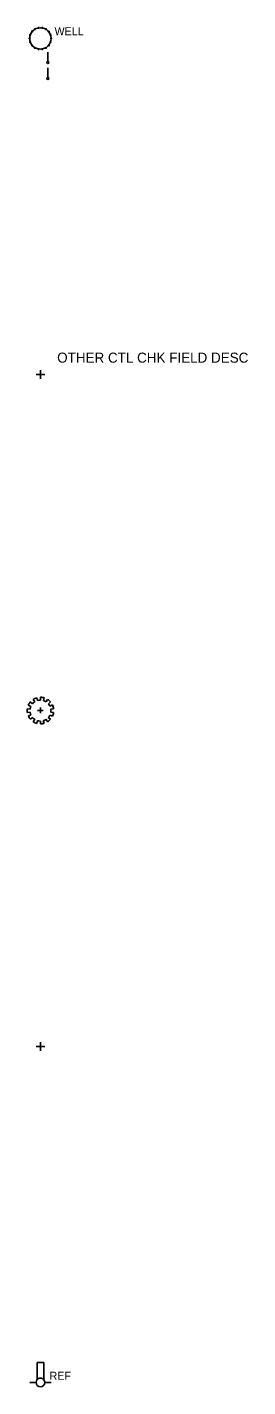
# Model space of a CAD drawing. Extents: x 98 to 2902, y -6 to 903.
# Drawn here: x 1498 to 1531, y 449.3 to 651.7 of the extents above; entities that cross this region are included whole.
import ezdxf

# ---------------------------------------------------------------- set-up
doc = ezdxf.new("R2010")
doc.units = 0
for name, color, linetype in [('V-CHAN-NAID', 7, 'Continuous'), ('V-FUEL-DEVC', 7, 'Continuous'), ('V-SITE-OTLN', 7, 'Continuous'), ('V-SITE-VEGE', 7, 'Continuous'), ('V-SURV-DATA', 7, 'Continuous')]:
    doc.layers.add(name, color=color, linetype=linetype)

msp = doc.modelspace()

# ---------------------------------------------------------------- linework, layer by layer
at = {"layer": 'V-CHAN-NAID'}
for p, q in [((1500.49, 452.95), (1499.51, 452.95)), ((1499.51, 452.95), (1499.51, 450.43)), ((1500.49, 450.43), (1500.49, 452.95)), ((1498.41, 450), (1499.35, 450)), ((1499.51, 450.43), (1499.51, 450.43)), ((1500.65, 450), (1501.59, 450))]:
    msp.add_line(p, q, dxfattribs=at)
msp.add_circle((1500, 450), 0.655, dxfattribs=at)
msp.add_arc((1500, 450), 0.655, 41.4079, 138.5909, dxfattribs=at)
at = {"layer": 'V-FUEL-DEVC'}
for p, q in [((1499.72, 651.59), (1499.72, 651.59)), ((1500.28, 651.59), (1500.28, 651.59)), ((1498.39, 650), (1498.39, 650)), ((1498.48, 650.55), (1498.48, 650.55)), ((1498.76, 651.04), (1498.76, 651.04)), ((1499.19, 651.4), (1499.19, 651.4)), ((1500.81, 651.4), (1500.81, 651.4)), ((1501.24, 651.04), (1501.24, 651.04)), ((1501.52, 650.55), (1501.52, 650.55)), ((1501.61, 650), (1501.61, 650)), ((1498.48, 649.45), (1498.48, 649.45)), ((1498.76, 648.96), (1498.76, 648.96)), ((1499.19, 648.6), (1499.19, 648.6)), ((1499.72, 648.41), (1499.72, 648.41)), ((1500.28, 648.41), (1500.28, 648.41)), ((1500.81, 648.6), (1500.81, 648.6)), ((1501.12, 647.98), (1501.12, 646.55)), ((1501.24, 648.96), (1501.24, 648.96)), ((1501.52, 649.45), (1501.52, 649.45)), ((1501.12, 645.62), (1501.12, 644.19))]:
    msp.add_line(p, q, dxfattribs=at)
for centre, radius in [((1500, 650), 1.59), ((1499.72, 651.59), 0.0717), ((1500.28, 651.59), 0.0717), ((1498.39, 650), 0.0717), ((1498.48, 650.55), 0.0717), ((1498.48, 649.45), 0.0717), ((1498.76, 651.04), 0.0717), ((1499.19, 651.4), 0.0717), ((1500.81, 651.4), 0.0717), ((1501.24, 651.04), 0.0717), ((1501.52, 650.55), 0.0717), ((1501.52, 649.45), 0.0717), ((1501.61, 650), 0.0717), ((1498.76, 648.96), 0.0717), ((1499.19, 648.6), 0.0717), ((1499.72, 648.41), 0.0717), ((1500.28, 648.41), 0.0717), ((1500.81, 648.6), 0.0717), ((1501.24, 648.96), 0.0717), ((1501.12, 646.41), 0.143), ((1501.12, 644.04), 0.143)]:
    msp.add_circle(centre, radius, dxfattribs=at)
at = {"layer": 'V-SITE-OTLN'}
for p, q in [((1500, 500), (1499.35, 500)), ((1500, 500.65), (1500, 499.35)), ((1500, 500), (1500.65, 500))]:
    msp.add_line(p, q, dxfattribs=at)
at = {"layer": 'V-SITE-VEGE'}
for p, q in [((1498.58, 550.61), (1498.19, 550.78)), ((1498.49, 551.26), (1498.81, 550.98)), ((1499.17, 551.3), (1498.93, 551.65)), ((1499.46, 551.89), (1499.56, 551.47)), ((1500, 551.53), (1500.01, 551.96)), ((1500, 550.42), (1500, 549.58)), ((1500.57, 551.88), (1500.45, 551.47)), ((1500.84, 551.29), (1501.08, 551.64)), ((1501.51, 551.27), (1501.19, 550.99)), ((1501.42, 550.62), (1501.8, 550.82)), ((1498.03, 550.25), (1498.46, 550.18)), ((1498.46, 549.76), (1498.04, 549.69)), ((1498.19, 549.16), (1498.58, 549.35)), ((1498.83, 548.96), (1498.5, 548.68)), ((1498.94, 548.3), (1499.15, 548.68)), ((1499.58, 548.48), (1499.46, 548.07)), ((1499.58, 550), (1500.42, 550)), ((1500, 547.99), (1500, 548.42)), ((1500.43, 548.49), (1500.56, 548.08)), ((1501.08, 548.31), (1500.85, 548.68)), ((1501.17, 548.95), (1501.5, 548.68)), ((1501.81, 549.15), (1501.41, 549.31)), ((1501.97, 550.25), (1501.54, 550.19)), ((1501.54, 549.75), (1501.97, 549.7))]:
    msp.add_line(p, q, dxfattribs=at)
for radius, start, end in [(1.98, 139.7777, 156.0738), (1.56, 156.0557, 172.7558), (1.56, 122.254, 140.086), (1.98, 105.972, 122.5562), (1.56, 89.9461, 106.3473), (1.98, 73.2952, 89.5718), (1.56, 57.451, 73.0843), (1.98, 40.7122, 57.1166), (1.56, 24.4529, 40.4774), (1.98, 7.9671, 24.8625), (1.98, 172.27, 188.583), (1.98, 204.5394, 220.9852), (1.56, 188.0619, 204.0332), (1.56, 221.2062, 236.7795), (1.56, 254.31, 270.043), (1.56, 285.9559, 303.0564), (1.98, 302.8434, 319.0222), (1.56, 318.6432, 334.5795), (1.56, 351.5431, 7.6203), (1.98, 335.3123, 351.7042), (1.98, 237.6108, 254.1981), (1.98, 270.0356, 286.342)]:
    msp.add_arc((1500, 549.98), radius, start, end, dxfattribs=at)
at = {"layer": 'V-SURV-DATA'}
for p, q in [((1500, 600), (1499.35, 600)), ((1500, 600.65), (1500, 599.35)), ((1500, 600), (1500.65, 600))]:
    msp.add_line(p, q, dxfattribs=at)

# ---------------------------------------------------------------- texts
at = {"layer": 'V-CHAN-NAID'}
msp.add_text('REF', height=1.191, dxfattribs=at).set_placement((1501.37, 450.39))
msp.add_text('REF', height=1.191, dxfattribs=at).set_placement((1501.37, 450.39))
at = {"layer": 'V-FUEL-DEVC'}
msp.add_text('WELL', height=1.189, dxfattribs=at).set_placement((1502.11, 650.49))
at = {"layer": 'V-SURV-DATA'}
msp.add_text('OTHER CTL CHK FIELD DESC', height=1.5, dxfattribs=at).set_placement((1502.5, 601.75))

doc.saveas('drawing.dxf')
